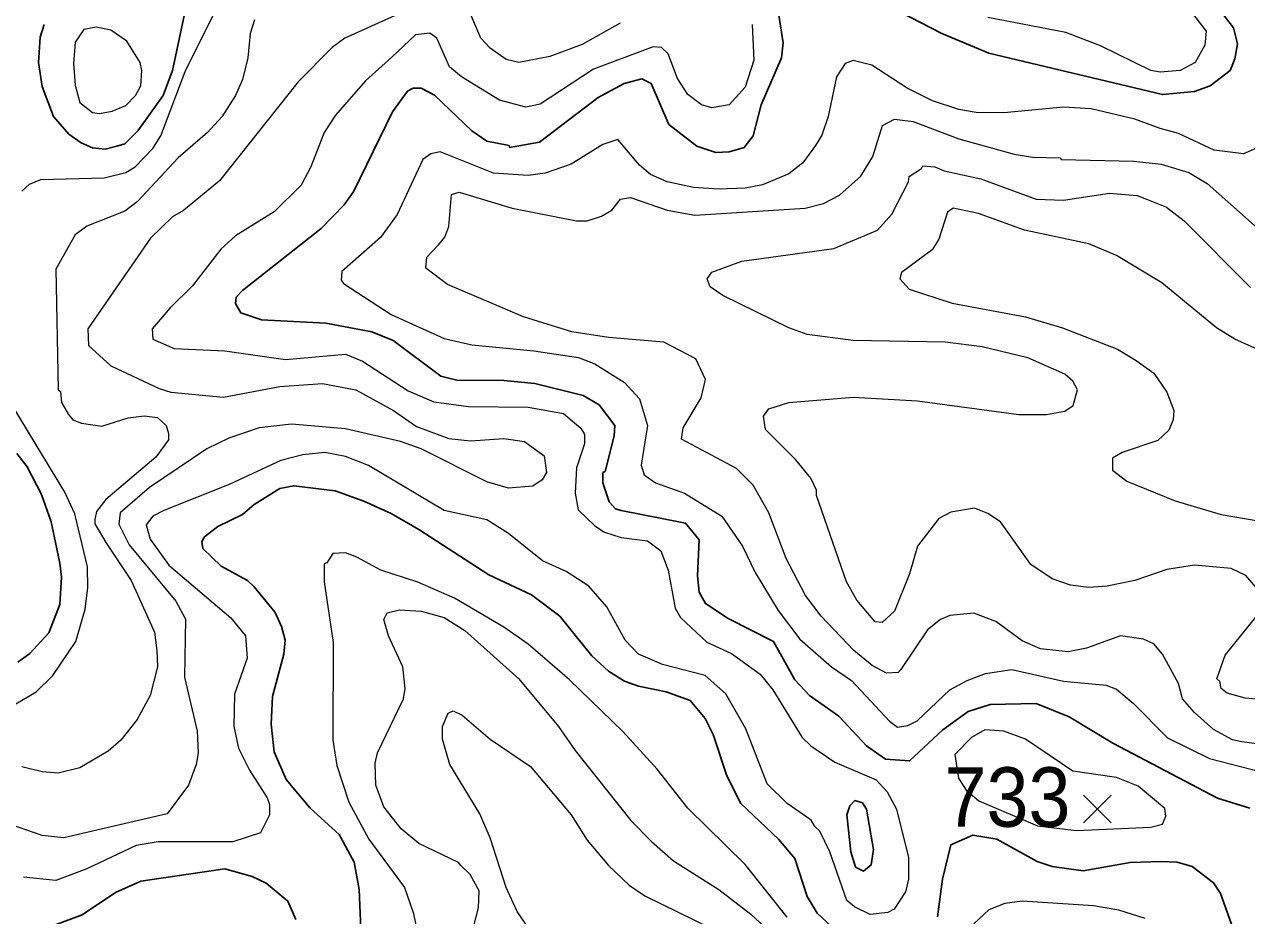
# Model space of a CAD drawing. Extents: x 423 to 448.8, y 7456.3 to 7484.
# Drawn here: x 432.377 to 434.022, y 7464.12 to 7465.32 of the extents above; entities that cross this region are included whole.
import ezdxf
from ezdxf.enums import TextEntityAlignment as Align

# ---------------------------------------------------------------- set-up
doc = ezdxf.new("R2010")
doc.units = 0
doc.header["$LTSCALE"] = 0.032
for name, color, linetype, lineweight in [('1', 7, 'Continuous', 25), ('2', 7, 'Continuous', 13), ('21', 7, 'Continuous', 25)]:
    doc.layers.add(name, color=color, linetype=linetype, lineweight=lineweight)
doc.layers.add('61', color=7, linetype='Continuous')

msp = doc.modelspace()

# ---------------------------------------------------------------- linework, layer by layer
at = {"layer": '1'}
for points in [[(433.3884, 7465.3586), (433.3984, 7465.2952), (433.3961, 7465.2751), (433.369, 7465.2117), (433.3582, 7465.1699), (433.3459, 7465.1544)], [(433.9878, 7465.337), (434.0048, 7465.3153), (434.0102, 7465.2937), (434.0064, 7465.2736), (434.0002, 7465.2581), (433.9731, 7465.2372), (433.9522, 7465.2295), (433.9089, 7465.2256), (433.6753, 7465.2813), (433.6119, 7465.3076), (433.5268, 7465.3516)], [(432.594, 7465.3401), (432.5762, 7465.2581), (432.5638, 7465.2241), (432.5298, 7465.1769), (432.5121, 7465.1591), (432.5012, 7465.156), (432.4858, 7465.1521), (432.4688, 7465.1537), (432.4532, 7465.1606), (432.437, 7465.1722), (432.4161, 7465.1962), (432.4007, 7465.2364), (432.396, 7465.2689), (432.3984, 7465.303), (432.4038, 7465.32)], [(433.3459, 7465.1544), (433.3257, 7465.1483), (433.3079, 7465.1475), (433.2824, 7465.156), (433.2445, 7465.1854), (433.2206, 7465.2403), (433.2082, 7465.2465), (433.1842, 7465.2403), (433.1494, 7465.2217), (433.0705, 7465.1614), (433.0302, 7465.1544), (433.0295, 7465.1568), (432.9993, 7465.1629), (432.9792, 7465.1769), (432.9289, 7465.2248), (432.9112, 7465.2341), (432.9003, 7465.2341), (432.8926, 7465.2302), (432.8725, 7465.2024), (432.8206, 7465.0957), (432.8075, 7465.0771), (432.7766, 7465.0454), (432.6706, 7464.9618), (432.6621, 7464.9526), (432.6613, 7464.9441), (432.6683, 7464.9317), (432.6961, 7464.9224), (432.7828, 7464.9178), (432.8447, 7464.9062), (432.8732, 7464.8946), (432.9375, 7464.8466), (432.9591, 7464.8412), (433.0225, 7464.8404), (433.0643, 7464.8365), (433.1293, 7464.8203), (433.1509, 7464.8079), (433.1718, 7464.7801), (433.171, 7464.7662), (433.1587, 7464.7182), (433.1556, 7464.7166), (433.1556, 7464.7028), (433.1641, 7464.6772), (433.1726, 7464.6679), (433.1803, 7464.6656), (433.267, 7464.6486), (433.2855, 7464.6262), (433.2832, 7464.5775), (433.2855, 7464.5558), (433.294, 7464.5403), (433.3242, 7464.5202), (433.3853, 7464.4893), (433.4139, 7464.4374), (433.434, 7464.4165), (433.4734, 7464.3887), (433.5106, 7464.3485), (433.5361, 7464.3307), (433.5686, 7464.3284), (433.6135, 7464.3701), (433.6475, 7464.3949), (433.6769, 7464.4042), (433.7388, 7464.4057), (433.7836, 7464.3879), (433.8424, 7464.3523), (433.9832, 7464.2781), (434.0265, 7464.265)], [(432.3666, 7464.7422), (432.3805, 7464.7244), (432.3999, 7464.6873), (432.413, 7464.6502), (432.4246, 7464.5945), (432.427, 7464.5759), (432.4246, 7464.5388), (432.4099, 7464.5009), (432.3844, 7464.473), (432.3682, 7464.4614)], [(433.4632, 7464.1058), (433.4441, 7464.1234), (433.4309, 7464.1459), (433.4139, 7464.1969), (433.3923, 7464.2232), (433.3412, 7464.2712), (433.3226, 7464.3083), (433.3041, 7464.364), (433.2932, 7464.3856), (433.2731, 7464.4096), (433.2407, 7464.4212), (433.2035, 7464.4289), (433.185, 7464.4359), (433.1633, 7464.4491), (433.1408, 7464.4699), (433.0976, 7464.5233), (433.0597, 7464.5519), (433.0024, 7464.579), (432.9081, 7464.6401), (432.8709, 7464.6617), (432.8338, 7464.678), (432.7952, 7464.6919), (432.7395, 7464.6989), (432.7209, 7464.695), (432.6861, 7464.6734), (432.6706, 7464.6602), (432.6374, 7464.6439), (432.6195, 7464.63), (432.6157, 7464.6238), (432.6172, 7464.6146), (432.642, 7464.5906), (432.6775, 7464.5712), (432.6861, 7464.5627), (432.7147, 7464.528), (432.7232, 7464.5094), (432.7278, 7464.4908), (432.7263, 7464.4723), (432.7108, 7464.415), (432.7093, 7464.3779), (432.7132, 7464.3408), (432.7294, 7464.3036), (432.7619, 7464.2649), (432.8006, 7464.2294), (432.8207, 7464.1923), (432.8276, 7464.1551), (432.8307, 7464.0809)], [(433.8022, 7464.1806), (433.7604, 7464.1861), (433.7403, 7464.193), (433.6861, 7464.2232), (433.6537, 7464.2286), (433.6243, 7464.2155), (433.6127, 7464.1691), (433.6063, 7464.1187)], [(432.7425, 7464.1149), (432.7317, 7464.1396), (432.7023, 7464.1636), (432.6838, 7464.1729), (432.6466, 7464.183), (432.5337, 7464.1667), (432.4997, 7464.1513), (432.4548, 7464.1211), (432.4177, 7464.1072)], [(434.035, 7464.0639), (434.0164, 7464.0785), (434.004, 7464.1025), (433.987, 7464.1497), (433.9777, 7464.1644), (433.9492, 7464.1861), (433.929, 7464.1923), (433.9074, 7464.193), (433.8656, 7464.1915), (433.8022, 7464.1806)]]:
    msp.add_lwpolyline(points, dxfattribs=at)
msp.add_lwpolyline([(433.5105, 7464.2634), (433.5051, 7464.2719), (433.4951, 7464.275), (433.4881, 7464.268), (433.4843, 7464.2557), (433.4897, 7464.2062), (433.4959, 7464.1853), (433.5067, 7464.1799), (433.5168, 7464.1884), (433.5199, 7464.2093)], close=True, dxfattribs=at)
at = {"layer": '2'}
for points in [[(433.1788, 7465.3215), (433.1277, 7465.2929), (433.0844, 7465.2767), (433.0427, 7465.2689), (433.0256, 7465.2728), (433.004, 7465.2882), (432.9916, 7465.3014), (432.9715, 7465.3478)], [(432.3736, 7465.0957), (432.3837, 7465.1049), (432.3991, 7465.1111), (432.4842, 7465.1134), (432.5136, 7465.1204), (432.5259, 7465.1282), (432.5499, 7465.1529), (432.5608, 7465.1699), (432.5932, 7465.2566), (432.6366, 7465.3432)], [(432.8802, 7465.3339), (432.8083, 7465.3014), (432.7913, 7465.289), (432.7456, 7465.2426)], [(433.9445, 7465.3408), (433.9677, 7465.3107), (433.9662, 7465.2921), (433.953, 7465.2689), (433.9329, 7465.2581), (433.9058, 7465.2558), (433.8935, 7465.2581), (433.8254, 7465.2913), (433.779, 7465.3091), (433.6738, 7465.3293)], [(432.6869, 7465.3262), (432.6807, 7465.3076), (432.6776, 7465.2751), (432.6706, 7465.2457), (432.6613, 7465.2241), (432.6427, 7465.1954), (432.6234, 7465.1745), (432.584, 7465.1405), (432.5291, 7465.0817), (432.5121, 7465.0686), (432.461, 7465.0485), (432.4455, 7465.0368), (432.4192, 7464.9905), (432.4223, 7464.8281), (432.4254, 7464.8257), (432.4269, 7464.811), (432.4362, 7464.7948), (432.4424, 7464.7878), (432.454, 7464.7832), (432.4811, 7464.7793), (432.5167, 7464.7901), (432.5384, 7464.7932), (432.5561, 7464.7909), (432.5677, 7464.7801), (432.5708, 7464.7693), (432.5708, 7464.7607), (432.5538, 7464.7375), (432.4865, 7464.6803), (432.4742, 7464.6641), (432.4718, 7464.6533), (432.4718, 7464.6478), (432.4865, 7464.6223), (432.5205, 7464.5713), (432.5523, 7464.5016), (432.5554, 7464.4769), (432.5561, 7464.4552), (432.5461, 7464.4166), (432.529, 7464.3841), (432.5066, 7464.3562), (432.4896, 7464.3415), (432.4517, 7464.3191), (432.4223, 7464.3121), (432.4007, 7464.3137), (432.3736, 7464.3206)], [(433.3567, 7465.32), (433.359, 7465.272), (433.3474, 7465.2356), (433.3257, 7465.2117), (433.3025, 7465.2078), (433.2886, 7465.2117), (433.27, 7465.2256), (433.2561, 7465.2473), (433.2437, 7465.2805), (433.2345, 7465.289), (433.2236, 7465.2898), (433.1432, 7465.2596), (433.0712, 7465.2124), (433.0519, 7465.2086)], [(433.0519, 7465.2086), (433.0164, 7465.2179), (432.9653, 7465.2496), (432.9491, 7465.2627), (432.932, 7465.3014), (432.9228, 7465.3084), (432.9034, 7465.306), (432.8717, 7465.2759), (432.8361, 7465.2441), (432.7959, 7465.1978), (432.7804, 7465.1746), (432.7627, 7465.1282), (432.7495, 7465.1034), (432.7132, 7465.0678), (432.6613, 7465.0353), (432.6412, 7465.0175), (432.6033, 7464.968), (432.5731, 7464.9386), (432.5492, 7464.91), (432.5499, 7464.8961), (432.5786, 7464.8837), (432.6466, 7464.8806), (432.7286, 7464.869), (432.8091, 7464.876), (432.8323, 7464.8667), (432.8934, 7464.8265), (432.9282, 7464.8118), (432.9746, 7464.8056), (433.055, 7464.8048), (433.1029, 7464.7963), (433.1262, 7464.7762), (433.1308, 7464.7677), (433.1308, 7464.7553), (433.12, 7464.7229), (433.1184, 7464.6888), (433.1223, 7464.6664), (433.1447, 7464.6447), (433.1579, 7464.6362), (433.1803, 7464.6292), (433.2159, 7464.6246), (433.2337, 7464.6114), (433.2438, 7464.5852), (433.253, 7464.5341), (433.26, 7464.5217), (433.2956, 7464.4885), (433.3288, 7464.473), (433.3675, 7464.4452), (433.3845, 7464.4243), (433.4239, 7464.3601), (433.4355, 7464.3485), (433.4681, 7464.3268), (433.5238, 7464.3028), (433.5384, 7464.2866), (433.5508, 7464.2634), (433.5671, 7464.1984), (433.5671, 7464.1691), (433.5632, 7464.152), (433.5477, 7464.1288), (433.5393, 7464.1245), (433.5153, 7464.1215), (433.4943, 7464.1319), (433.4843, 7464.1404), (433.4611, 7464.2062), (433.4479, 7464.234), (433.441, 7464.2402), (433.4363, 7464.2487), (433.4038, 7464.2712), (433.3768, 7464.2975), (433.3481, 7464.3717), (433.3211, 7464.4189), (433.2933, 7464.4436), (433.236, 7464.4583), (433.2035, 7464.4722), (433.1857, 7464.4908), (433.161, 7464.5357), (433.137, 7464.5635), (433.1061, 7464.5836), (433.0743, 7464.5976), (433.0287, 7464.6346), (432.9993, 7464.6532), (432.9421, 7464.6656), (432.84, 7464.726), (432.8091, 7464.7383), (432.7812, 7464.7437), (432.7518, 7464.7406), (432.7224, 7464.7329), (432.6528, 7464.7004), (432.5647, 7464.6656), (432.5499, 7464.6579), (432.5407, 7464.6463), (432.5461, 7464.627), (432.5716, 7464.5921), (432.6551, 7464.521), (432.6745, 7464.497), (432.6768, 7464.4668), (432.6598, 7464.4181), (432.659, 7464.3748), (432.6652, 7464.3454), (432.6799, 7464.316), (432.7039, 7464.2789), (432.707, 7464.2696)], [(434.042, 7465.156), (434.018, 7465.1459), (433.9785, 7465.1506), (433.9306, 7465.173), (433.9058, 7465.1799), (433.8718, 7465.1923), (433.813, 7465.2063), (433.7759, 7465.2086), (433.6955, 7465.2009), (433.6583, 7465.2016), (433.6351, 7465.2055), (433.5995, 7465.2171), (433.5655, 7465.2341), (433.5176, 7465.265), (433.4928, 7465.2712), (433.4819, 7465.2674), (433.4704, 7465.2496), (433.4588, 7465.1962), (433.4503, 7465.1707), (433.4418, 7465.1568), (433.4247, 7465.1336), (433.4062, 7465.1189), (433.3706, 7465.1041), (433.3474, 7465.0995), (433.3118, 7465.098), (433.2778, 7465.1003), (433.2422, 7465.108), (433.2197, 7465.1181), (433.2051, 7465.1305), (433.1757, 7465.1652), (433.1556, 7465.1583), (433.113, 7465.132), (433.0782, 7465.1196), (433.055, 7465.1165), (433.0086, 7465.1196), (432.9367, 7465.1483), (432.9243, 7465.1459), (432.9135, 7465.1382), (432.8787, 7465.0639), (432.8562, 7465.033), (432.8044, 7464.9873), (432.8036, 7464.9758), (432.8067, 7464.9711), (432.8709, 7464.9293), (432.9421, 7464.8969), (432.9792, 7464.8884), (433.0628, 7464.8806), (433.1231, 7464.8714), (433.1448, 7464.8628), (433.1849, 7464.8381), (433.205, 7464.8157), (433.2159, 7464.7801), (433.2074, 7464.7267), (433.2113, 7464.7135), (433.2267, 7464.7027), (433.2654, 7464.6888), (433.3157, 7464.6579), (433.3435, 7464.6177), (433.3605, 7464.5821), (433.3915, 7464.531), (433.4208, 7464.4923), (433.4634, 7464.4552), (433.4905, 7464.4367), (433.5415, 7464.3817), (433.5523, 7464.374), (433.5663, 7464.3763), (433.5786, 7464.3825), (433.6228, 7464.4243), (433.646, 7464.4367), (433.6707, 7464.4459), (433.7063, 7464.4513), (433.7759, 7464.4359), (433.8331, 7464.4305), (433.847, 7464.425), (433.8702, 7464.4057), (433.9159, 7464.3593), (433.9724, 7464.3315), (434.042, 7464.3137)], [(432.7456, 7465.2426), (432.6397, 7465.1096), (432.591, 7465.0693), (432.5762, 7465.0608), (432.5469, 7465.0322), (432.4625, 7464.91), (432.4633, 7464.8876), (432.4935, 7464.8605), (432.5585, 7464.8296), (432.5739, 7464.825), (432.6451, 7464.818), (432.7209, 7464.8327), (432.7781, 7464.8365), (432.823, 7464.828), (432.874, 7464.8002), (432.905, 7464.7785), (432.9483, 7464.7623), (432.9777, 7464.7592), (433.0225, 7464.7623), (433.0504, 7464.7584), (433.0767, 7464.7391), (433.0798, 7464.7167), (433.0741, 7464.7068), (433.0612, 7464.6981), (433.0287, 7464.6958), (432.9993, 7464.7043), (432.9112, 7464.7484), (432.8833, 7464.7584), (432.8091, 7464.7755), (432.7364, 7464.7816), (432.6931, 7464.777), (432.652, 7464.7631), (432.6226, 7464.7484), (432.5453, 7464.6965), (432.5058, 7464.6625), (432.5043, 7464.6471), (432.5182, 7464.6192), (432.5809, 7464.5434), (432.594, 7464.5194), (432.5925, 7464.4413), (432.6095, 7464.3686), (432.6111, 7464.3392), (432.608, 7464.3238), (432.5979, 7464.2959), (432.5693, 7464.2572), (432.4301, 7464.2248), (432.4007, 7464.2278), (432.328, 7464.2533)], [(433.4936, 7464.4769), (433.4495, 7464.5233), (433.4286, 7464.5512), (433.4023, 7464.6007), (433.3791, 7464.6625), (433.3582, 7464.6997), (433.3358, 7464.7221), (433.2615, 7464.7615), (433.2639, 7464.777), (433.2878, 7464.8172), (433.294, 7464.842), (433.2809, 7464.8698), (433.2376, 7464.8922), (433.1633, 7464.8984), (433.1138, 7464.9061), (433.0488, 7464.9263), (432.9467, 7464.9696), (432.9174, 7464.992), (432.9189, 7465.0067), (432.9344, 7465.023), (432.9428, 7465.0337), (432.9483, 7465.0477), (432.9521, 7465.091), (432.9622, 7465.0941), (433.0334, 7465.0725), (433.12, 7465.0554), (433.1347, 7465.0554), (433.154, 7465.0616), (433.1679, 7465.0701), (433.1795, 7465.0848), (433.1927, 7465.0871), (433.2422, 7465.0701), (433.2793, 7465.0631), (433.4278, 7465.0725), (433.4526, 7465.0787), (433.4742, 7465.0902), (433.5028, 7465.1158), (433.5191, 7465.1421), (433.5322, 7465.1838), (433.5485, 7465.1923), (433.5733, 7465.1892), (433.6351, 7465.166), (433.7094, 7465.1452), (433.7341, 7465.1413), (433.7713, 7465.1405), (433.7728, 7465.1382), (433.8703, 7465.1359), (433.9074, 7465.132), (433.9445, 7465.1204), (433.9693, 7465.1057), (434.0605, 7465.0245)], [(433.7945, 7464.8281), (433.7882, 7464.8396), (433.7774, 7464.8489), (433.7279, 7464.8713), (433.6661, 7464.886), (433.6166, 7464.8922), (433.4928, 7464.8946), (433.4309, 7464.9023), (433.4062, 7464.9115), (433.3172, 7464.9549), (433.3002, 7464.9665), (433.2963, 7464.9773), (433.3025, 7464.9866), (433.3428, 7465.0013), (433.4665, 7465.0183), (433.5253, 7465.0431), (433.5446, 7465.0647), (433.567, 7465.108), (433.5678, 7465.115), (433.5848, 7465.1258), (433.5864, 7465.1297), (433.6026, 7465.1282), (433.615, 7465.1227), (433.6645, 7465.1119), (433.7388, 7465.0848), (433.7759, 7465.0833), (433.8378, 7465.0926), (433.8749, 7465.0895), (433.8873, 7465.0848), (433.9143, 7465.074), (433.9383, 7465.0555), (434.0273, 7464.9657)], [(433.8471, 7465.009), (433.8099, 7465.0245), (433.7233, 7465.043), (433.6614, 7465.0655), (433.6274, 7465.0724), (433.6197, 7465.067), (433.608, 7465.0307), (433.5988, 7465.0167), (433.5577, 7464.9858), (433.5554, 7464.9773), (433.5678, 7464.9634), (433.6258, 7464.9448), (433.7248, 7464.9263), (433.7744, 7464.9116), (433.8486, 7464.8829), (433.8734, 7464.8675), (433.8973, 7464.8505), (433.9151, 7464.825), (433.9244, 7464.8002), (433.9236, 7464.7878), (433.9174, 7464.7739), (433.9027, 7464.76), (433.8548, 7464.7437), (433.8416, 7464.736), (433.8416, 7464.7197), (433.8609, 7464.705), (433.9259, 7464.6787), (433.9878, 7464.6602), (434.0745, 7464.6455)], [(434.1224, 7464.8443), (434.0064, 7464.8961), (433.9816, 7464.9115), (433.9081, 7464.9719), (433.8471, 7465.009)], [(434.0404, 7464.5558), (434.0211, 7464.5782), (434.0017, 7464.5875), (433.9522, 7464.5921), (433.9151, 7464.5859), (433.8718, 7464.5713), (433.8347, 7464.5635), (433.8099, 7464.562), (433.7852, 7464.5651), (433.7604, 7464.5736), (433.7318, 7464.5929), (433.6908, 7464.6502), (433.6738, 7464.6617), (433.656, 7464.6687), (433.6243, 7464.6633), (433.608, 7464.6548), (433.5794, 7464.6177), (433.5686, 7464.5805), (433.5485, 7464.5302), (433.5315, 7464.5148), (433.5222, 7464.5156), (433.4974, 7464.545), (433.4835, 7464.5697), (433.4433, 7464.6857), (433.4433, 7464.6927), (433.4356, 7464.7089), (433.4155, 7464.7337), (433.3745, 7464.7747), (433.3721, 7464.7925), (433.3791, 7464.8025), (433.4062, 7464.811), (433.4928, 7464.818), (433.5794, 7464.8133), (433.7156, 7464.7948), (433.7527, 7464.7948), (433.7774, 7464.7994), (433.789, 7464.8071), (433.7945, 7464.8281)], [(432.3558, 7464.3996), (432.3929, 7464.4212), (432.4154, 7464.4436), (432.4463, 7464.4893), (432.4587, 7464.5326), (432.4626, 7464.562), (432.4618, 7464.5898), (432.4447, 7464.661), (432.4316, 7464.6904), (432.362, 7464.8049)], [(433.4038, 7464.118), (433.3474, 7464.1891), (433.27, 7464.2649), (433.229, 7464.3175), (433.1826, 7464.3678), (433.1107, 7464.4374), (433.055, 7464.4854), (433.0225, 7464.5086), (432.956, 7464.5473), (432.9065, 7464.5689), (432.857, 7464.5851), (432.8245, 7464.6029), (432.8091, 7464.6084), (432.792, 7464.6076), (432.7843, 7464.5952), (432.7804, 7464.5937), (432.7804, 7464.5697), (432.7928, 7464.4877), (432.7921, 7464.3562), (432.7975, 7464.3222), (432.8137, 7464.2727), (432.8408, 7464.2232), (432.8887, 7464.1582), (432.9003, 7464.1242), (432.9111, 7464.0747)], [(432.9769, 7464.0871), (432.9885, 7464.1304), (432.9893, 7464.1536), (432.9769, 7464.1753), (432.9645, 7464.1876), (432.9614, 7464.1915), (432.9081, 7464.217), (432.8841, 7464.2371), (432.8609, 7464.2665), (432.85, 7464.2959), (432.8493, 7464.3253), (432.8524, 7464.3392), (432.8872, 7464.4119), (432.8895, 7464.4259), (432.8864, 7464.4552), (432.867, 7464.497), (432.8609, 7464.5186), (432.8655, 7464.5279), (432.8818, 7464.5318), (432.9112, 7464.5302), (432.9421, 7464.5217), (432.97, 7464.5039), (433.0426, 7464.439), (433.096, 7464.3748), (433.1184, 7464.3423), (433.1935, 7464.248), (433.2213, 7464.2201), (433.2507, 7464.1938), (433.3118, 7464.1551), (433.3551, 7464.1219), (433.4262, 7464.0561)], [(434.0528, 7464.3493), (434.0157, 7464.3539), (434.0033, 7464.357), (433.9778, 7464.3709), (433.9522, 7464.3934), (433.936, 7464.4119), (433.9305, 7464.4328), (433.9089, 7464.4723), (433.8973, 7464.4861), (433.8834, 7464.4924), (433.8525, 7464.497), (433.8068, 7464.48), (433.7821, 7464.4753), (433.745, 7464.4792), (433.7202, 7464.49), (433.6846, 7464.5163), (433.6552, 7464.5271), (433.6228, 7464.5241), (433.6104, 7464.5186), (433.5926, 7464.5047), (433.557, 7464.4514), (433.5531, 7464.4475), (433.5376, 7464.4467), (433.5183, 7464.4568), (433.4936, 7464.4769)], [(434.0396, 7464.4111), (434.0203, 7464.4127), (433.9963, 7464.4196), (433.9878, 7464.4258), (433.9863, 7464.4351), (433.9824, 7464.439), (433.9932, 7464.4707), (434.0365, 7464.5241)], [(433.0519, 7464.1087), (433.0403, 7464.1258), (433.0256, 7464.1582), (433.0039, 7464.2248), (432.9901, 7464.2572), (432.9498, 7464.3238), (432.9398, 7464.3578), (432.9398, 7464.3748), (432.9475, 7464.3926), (432.9544, 7464.3957)], [(432.9544, 7464.3957), (432.9661, 7464.3902), (433.004, 7464.3578), (433.0581, 7464.3207), (433.113, 7464.2557), (433.1347, 7464.2217), (433.1633, 7464.1876), (433.1912, 7464.1613), (433.212, 7464.1466), (433.301, 7464.1033)], [(432.707, 7464.2696), (432.707, 7464.2557), (432.6946, 7464.2317), (432.6575, 7464.2193), (432.5569, 7464.2193), (432.5275, 7464.2147), (432.461, 7464.1829), (432.4192, 7464.1675), (432.3759, 7464.1721)], [(433.8857, 7464.1164), (433.8502, 7464.1273), (433.8161, 7464.1335), (433.7202, 7464.1397), (433.697, 7464.1366), (433.6753, 7464.128), (433.649, 7464.1033)]]:
    msp.add_lwpolyline(points, dxfattribs=at)
for points in [[(432.495, 7465.2031), (432.5136, 7465.2109), (432.5267, 7465.2241), (432.5337, 7465.2372), (432.5353, 7465.2581), (432.5329, 7465.2689), (432.5151, 7465.2975), (432.4935, 7465.3122), (432.4734, 7465.3161), (432.4571, 7465.313), (432.4455, 7465.296), (432.4432, 7465.2674), (432.4455, 7465.238), (432.4517, 7465.2147), (432.4688, 7465.2016), (432.478, 7465.2001)], [(433.9135, 7464.2541), (433.912, 7464.2642), (433.8764, 7464.2943), (433.8471, 7464.3059), (433.7883, 7464.3145), (433.7248, 7464.3578), (433.6955, 7464.3686), (433.6699, 7464.3701), (433.6521, 7464.3601), (433.6297, 7464.3369), (433.6343, 7464.3051), (433.6447, 7464.289), (433.6617, 7464.2748), (433.7408, 7464.241), (433.7933, 7464.2349), (433.8935, 7464.2394), (433.9089, 7464.2433)]]:
    msp.add_lwpolyline(points, close=True, dxfattribs=at)
at = {"layer": '21'}
for p, q in [((433.8025, 7464.2824), (433.84, 7464.2449)), ((433.84, 7464.2824), (433.8025, 7464.2449))]:
    msp.add_line(p, q, dxfattribs=at)

# ---------------------------------------------------------------- texts
at = {"layer": '61', "width": 0.95}
msp.add_text('733', height=0.08, dxfattribs=at).set_placement((433.7004, 7464.2398), align=Align.CENTER)

doc.saveas('drawing.dxf')
